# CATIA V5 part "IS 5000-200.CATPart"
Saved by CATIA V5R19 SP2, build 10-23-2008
Part number: IS 5000-200
Bounding box of the stored display mesh (mm): x -59.975 to 59.975, y -59.975 to 59.975, z 0 to 540
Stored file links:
  C:\Users\Bora\Desktop\3D Katı model\IS serisi\IS 5000\IS 5000-200.CATPart
  C:\Program Files\Dassault Systemes\B19\intel_a\reffiles\standard\MetricThickPitch.txt
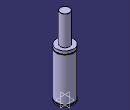
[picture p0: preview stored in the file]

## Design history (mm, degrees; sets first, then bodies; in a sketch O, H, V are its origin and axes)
Body1 (main body)
  Sketch1 on yz-plane, origin (0, 0, 0), H (0, 1, 0), V (0, 0, 1)
    point P1 (60, 317)
    point P4 (60, 312)
    point P7 (32.5, 539)
    point P9 (32.5, 539)
    point P13 (60, 317)
    point P14 (60, 312)
    line L1 (60, 317) -> (60, 337)
    line L2 (60, 13) -> (60, 312)
    line L3 (56, 13) -> (56, 8)
    arc A1 centre (31.5, 539) radius 1 from (32.5, 539) to (31.5, 540) ccw
    line L4 (32.5, 539) -> (32.5, 337)
    line L5 (60, 0) -> (60, 8)
    arc A2 centre (60, 314.5) radius 2.5 from (60, 317) to (60, 312) ccw
    line L6 (31.5, 540) -> (0, 540)
    point P15 (0, 540)
    line L7 (32.5, 337) -> (60, 337)
    line L8 (0, 0) -> (60, 0)
    line L9 (56, 13) -> (60, 13)
    line L10 (56, 8) -> (60, 8)
    coincidence: P15 V, P1 P13, P4 P14, P7 P9
    tangency: L6 A1
    horizontal: L7 H, L8 H, L9 H, L10 H
  Shaft1: profile Sketch1, axis Sketch1.V, angle 360
  Sketch2 on face of Shaft1 from Sketch1.L8, origin (0, 0, 0), H (1, 0, 0), V (0, -1, 0)
    point P1 (40, 0)
    distance P1 V = 40
  Hole1: placed by Sketch2, at (40, 0, 0) direction (0, 0, 1), diameter 8.376, depth 16, threaded "M10", thread diameter 10, thread depth 16, pitch 1.5
  CircPattern1: of Hole1, instances 4, angular step 90, axis from xy-plane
